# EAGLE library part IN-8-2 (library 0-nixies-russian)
IN-8-2: medium numeric frontview nixie tube
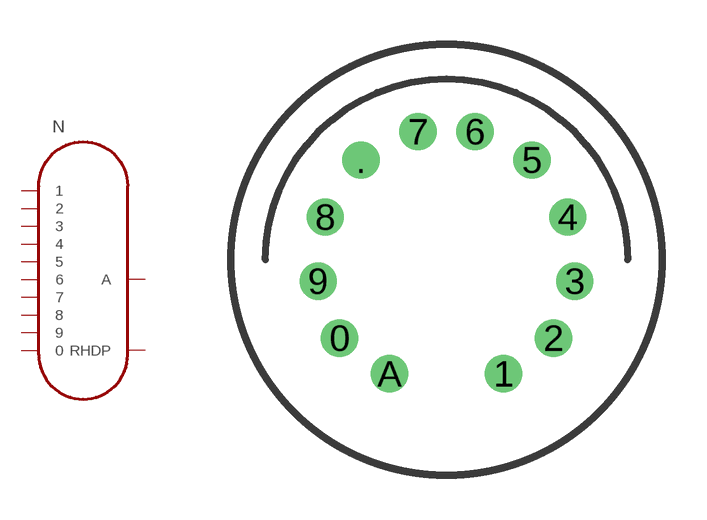
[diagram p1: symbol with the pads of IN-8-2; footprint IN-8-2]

Designator prefix N

## IN-8-2  [IN-8-2]
0  0
1  1
2  2
3  3
4  4
5  5
6  6
7  7
8  8
9  9
.  RHDP
A  A

## Footprint IN-8-2 (pad centres in mm)
drill 0.8 round: 0 -3.75,-2.75; 1 2,-4; 2 3.75,-2.75; 3 4.5,-0.75; 4 4.25,1.5; 5 3,3.5; 6 1,4.5; 7 -1,4.5; 8 -4.25,1.5; 9 -4.5,-0.75; . -3,3.5; A -2,-4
